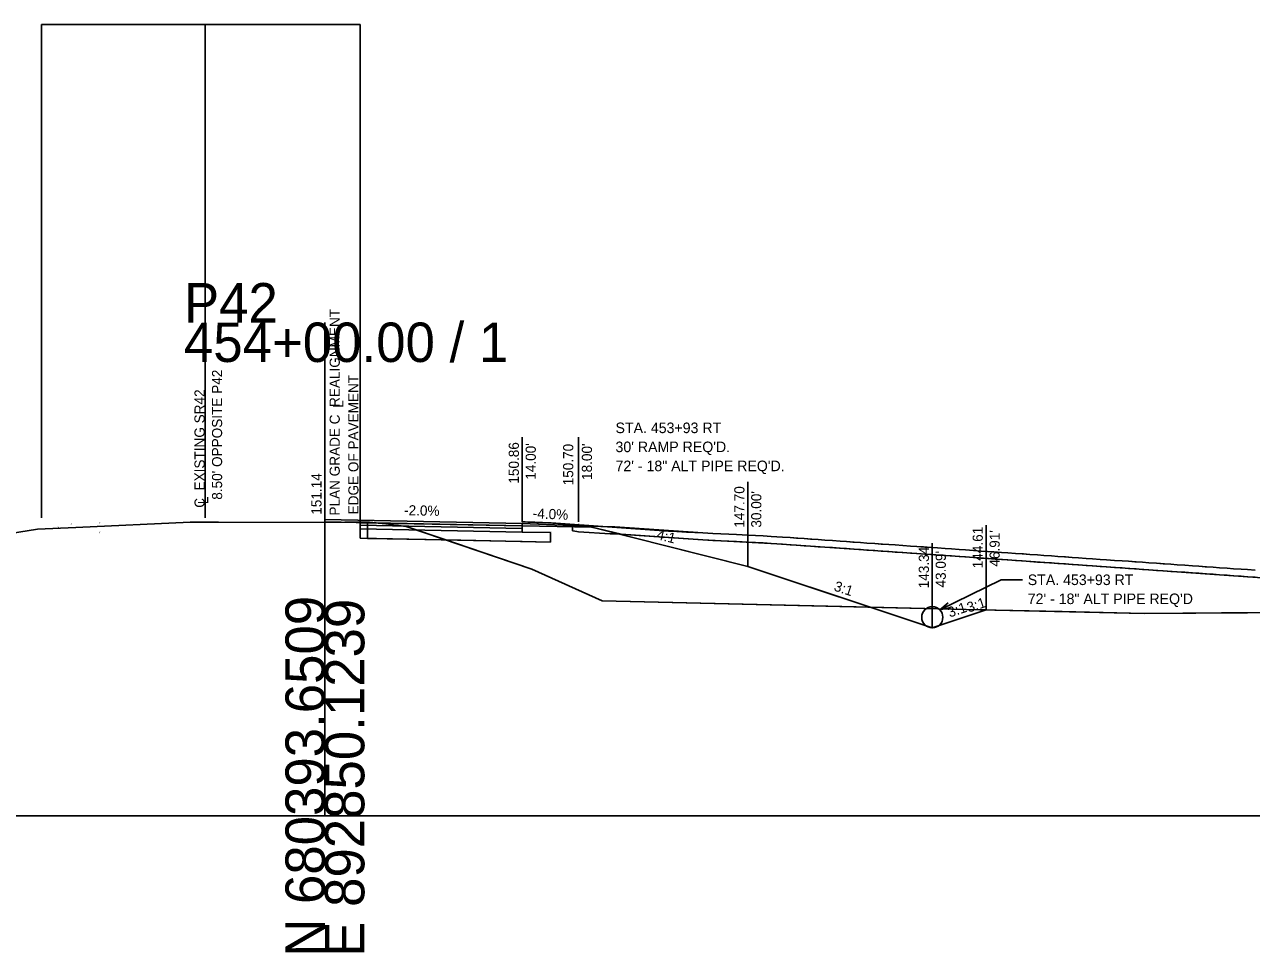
# Model space of a CAD drawing. Extents: x -26 to 4303, y -13 to 10775.
# Drawn here: x 128.7 to 215.7, y 2490.3 to 2556.1 of the extents above; entities that cross this region are included whole.
import ezdxf

# ---------------------------------------------------------------- set-up
doc = ezdxf.new("R2010")
doc.units = 0
for name, color, linetype in [('_CIVIL_CONSTRUCTION', 7, 'Continuous'), ('ASHPALT_12_5MM1', 7, 'Continuous'), ('CONST_DCH', 7, 'Continuous'), ('CONST_LV3', 7, 'Continuous'), ('Default', 7, 'Continuous'), ('DTM_CORRIDOR', 7, 'Continuous'), ('DTM_P_FINISHED_GRADE', 7, 'Continuous'), ('DTM_TEMP_DROP', 7, 'Continuous'), ('DTM_X_GROUND', 7, 'Continuous'), ('SLOPE_STAKES_FILL', 7, 'Continuous'), ('X_ROW', 7, 'Continuous'), ('X_TRANS_EOP', 7, 'Continuous'), ('XS_CELL', 7, 'Continuous'), ('XS_M_EXCAVATION_LIMITS', 7, 'Continuous'), ('XS_P_DR_GRAVEL', 7, 'Continuous'), ('XS_P_DRAINAGE', 7, 'Continuous'), ('XS_P_GROUND', 7, 'Continuous'), ('XS_P_SUBGRADE_MILLING', 7, 'Continuous'), ('XS_P_TX_CLEARZONE', 7, 'Continuous'), ('XS_P_TX_FS_BS', 7, 'Continuous'), ('XS_SHEET_EW_TX_AREA', 7, 'Continuous')]:
    doc.layers.add(name, color=color, linetype=linetype)

msp = doc.modelspace()

# ---------------------------------------------------------------- linework, layer by layer
msp.add_line((164, 2520.382), (164, 2520.132))
msp.add_lwpolyline([(152.49, 2520.613), (164, 2520.382), (164, 2520.57), (164, 2520.57), (152.49, 2520.8)])
at = {"layer": 'ASHPALT_12_5MM1'}
for p, q in [((164, 2520.736), (150, 2521.016)), ((164, 2520.57), (164, 2520.736))]:
    msp.add_line(p, q, dxfattribs=at)
at = {"layer": 'CONST_LV3'}
for points in [[(164, 2520.861), (164.203, 2520.853), (164.898, 2520.826), (165.026, 2520.82), (165.203, 2520.813), (165.819, 2520.789), (166.046, 2520.78), (174.373, 2520.208), (174.963, 2520.184), (175.657, 2520.134), (176.23, 2520.111), (176.802, 2520.088), (177.53, 2520.038), (178.089, 2520.016), (178.649, 2519.994), (179.208, 2519.971), (180, 2519.921), (180.55, 2519.899), (181.1, 2519.86), (181.65, 2519.822), (182.453, 2519.776), (183, 2519.737), (183.547, 2519.699), (184, 2519.667), (184.547, 2519.629), (185, 2519.597), (185.453, 2519.566), (186, 2519.527), (186.547, 2519.489), (187, 2519.457), (187.453, 2519.426), (188, 2519.387), (188.453, 2519.356), (189, 2519.317), (189.547, 2519.279), (190, 2519.247), (190.453, 2519.216), (191, 2519.177), (191.547, 2519.139), (192, 2519.107), (192.453, 2519.076), (193, 2519.037), (193.453, 2519.006), (194, 2518.967), (194.453, 2518.936), (195, 2518.897), (195.453, 2518.866), (196, 2518.827), (196.547, 2518.789), (197, 2518.757), (197.453, 2518.726), (198, 2518.687), (198.453, 2518.656), (199, 2518.617), (199.547, 2518.579), (200, 2518.547), (200.547, 2518.509), (201, 2518.477), (201.547, 2518.439), (202, 2518.407), (202.453, 2518.376), (203, 2518.337), (203.453, 2518.306), (204, 2518.267), (204.453, 2518.236), (205, 2518.197), (205.453, 2518.166), (206, 2518.127), (206.547, 2518.089), (207, 2518.057), (207.453, 2518.026), (208, 2517.987), (208.453, 2517.956), (209, 2517.917), (209.547, 2517.879), (210, 2517.847), (210.453, 2517.816), (211, 2517.777), (211.547, 2517.739), (212, 2517.707), (212.453, 2517.676), (213, 2517.637), (213.453, 2517.606), (214, 2517.567), (214.453, 2517.536), (215, 2517.497), (215.453, 2517.466), (216, 2517.427)], [(173.72, 2519.271), (180, 2517.701)]]:
    msp.add_lwpolyline(points, dxfattribs=at)
at = {"layer": 'Default'}
msp.add_lwpolyline([(150, 2521.016), (150, 2521.016), (150, 2521.016), (150, 2520.85), (150, 2520.85), (164, 2520.57), (164, 2520.736), (164, 2520.736), (150, 2521.016)], dxfattribs=at)
at = {"layer": 'DTM_P_FINISHED_GRADE'}
msp.add_lwpolyline([(164, 2520.861), (164.406, 2520.845), (165.43, 2520.803), (168, 2520.646)], dxfattribs=at)
at = {"layer": 'DTM_X_GROUND'}
msp.add_lwpolyline([(126.483, 2519.853), (129.624, 2520.342), (132.328, 2520.454), (140.446, 2520.825), (142.449, 2520.836), (150.002, 2520.811), (150.026, 2520.811), (153.025, 2520.845), (153.314, 2520.82), (154.313, 2520.72), (155.766, 2520.524), (164.68, 2517.505), (169.665, 2515.248), (196.459, 2514.625), (208.123, 2514.36), (219.103, 2514.434), (224.908, 2514.43), (258.789, 2514.528), (262.204, 2514.527), (283.454, 2514.615), (299.495, 2514.392), (300, 2514.385)], dxfattribs=at)
at = {"layer": 'X_ROW'}
for p, q in [((164, 2520.861), (164, 2520.861)), ((164, 2520.861), (164, 2520.861)), ((164, 2520.57), (164, 2520.736)), ((164, 2520.736), (168.595, 2520.553)), ((168.925, 2520.47), (164, 2520.57)), ((164, 2520.57), (164, 2520.57)), ((166, 2520.781), (166, 2520.781)), ((168, 2520.701), (168, 2520.701)), ((168.595, 2520.553), (168.925, 2520.47))]:
    msp.add_line(p, q, dxfattribs=at)
for points in [[(164, 2519.466), (166, 2519.426), (165.995, 2520.092), (165.995, 2520.092), (164, 2520.132), (164, 2520.132), (152.49, 2520.363)], [(152.49, 2519.696), (164, 2519.466), (164, 2519.466)]]:
    msp.add_lwpolyline(points, dxfattribs=at)
at = {"layer": 'X_TRANS_EOP'}
for p, q in [((129.887, 2521.141), (129.887, 2556.141)), ((129.887, 2556.141), (152.49, 2556.141)), ((141.5, 2521.141), (141.5, 2556.141)), ((152.49, 2521.141), (152.49, 2556.141))]:
    msp.add_line(p, q, dxfattribs=at)
at = {"layer": 'XS_CELL'}
for p, q in [((150, 2500), (150, 2535)), ((0, 2500), (150, 2500)), ((150, 2500), (300, 2500))]:
    msp.add_line(p, q, dxfattribs=at)
at = {"layer": 'XS_M_EXCAVATION_LIMITS'}
msp.add_line((152.49, 2519.696), (152.49, 2533.604), dxfattribs=at)
at = {"layer": 'XS_P_DR_GRAVEL'}
for p, q in [((167.575, 2520.216), (167.575, 2520.593)), ((170.242, 2520.51), (167.575, 2520.593)), ((170.242, 2520.51), (170.562, 2520.497)), ((170.562, 2520.497), (176.802, 2520.088)), ((167.58, 2520.215), (167.575, 2520.216)), ((167.583, 2520.215), (167.58, 2520.215)), ((167.607, 2520.214), (167.583, 2520.215)), ((168, 2520.146), (167.607, 2520.214)), ((170.242, 2520.01), (168, 2520.146)), ((170.562, 2519.997), (170.242, 2520.01)), ((176.802, 2519.588), (170.562, 2519.997)), ((176.802, 2520.088), (177.53, 2520.038)), ((177.53, 2520.038), (178.089, 2520.016)), ((178.089, 2520.016), (178.649, 2519.994)), ((178.649, 2519.994), (179.208, 2519.971)), ((179.208, 2519.971), (180, 2519.921)), ((180, 2519.921), (180.55, 2519.899)), ((180.55, 2519.899), (181.1, 2519.86)), ((181.1, 2519.86), (181.65, 2519.822)), ((181.65, 2519.822), (182.453, 2519.776)), ((182.453, 2519.776), (183, 2519.737)), ((183, 2519.737), (183.453, 2519.706)), ((183.453, 2519.706), (184, 2519.667)), ((184, 2519.667), (184.453, 2519.636)), ((184.453, 2519.636), (185, 2519.597)), ((177.53, 2519.538), (176.802, 2519.588)), ((178.089, 2519.516), (177.53, 2519.538)), ((178.649, 2519.494), (178.089, 2519.516)), ((179.208, 2519.471), (178.649, 2519.494)), ((180, 2519.421), (179.208, 2519.471)), ((180.55, 2519.399), (180, 2519.421)), ((181.1, 2519.36), (180.55, 2519.399)), ((181.65, 2519.322), (181.1, 2519.36)), ((182.453, 2519.276), (181.65, 2519.322)), ((183, 2519.237), (182.453, 2519.276)), ((183.453, 2519.206), (183, 2519.237)), ((184, 2519.167), (183.453, 2519.206)), ((184.453, 2519.136), (184, 2519.167)), ((185, 2519.097), (184.453, 2519.136)), ((185, 2519.597), (185.453, 2519.566)), ((185.453, 2519.066), (185, 2519.097)), ((185.453, 2519.566), (186, 2519.527)), ((186, 2519.027), (185.453, 2519.066)), ((186, 2519.527), (186.547, 2519.489)), ((186.547, 2518.989), (186, 2519.027)), ((186.547, 2519.489), (187, 2519.457)), ((187, 2518.957), (186.547, 2518.989)), ((187, 2519.457), (187.547, 2519.419)), ((187.547, 2518.919), (187, 2518.957)), ((187.547, 2519.419), (188, 2519.387)), ((188, 2518.887), (187.547, 2518.919)), ((188, 2519.387), (188.453, 2519.356)), ((188.453, 2518.856), (188, 2518.887)), ((188.453, 2519.356), (189, 2519.317)), ((189, 2518.817), (188.453, 2518.856)), ((189, 2519.317), (189.453, 2519.286)), ((189.453, 2518.786), (189, 2518.817)), ((189.453, 2519.286), (190, 2519.247)), ((190, 2518.747), (189.453, 2518.786)), ((190, 2519.247), (190.453, 2519.216)), ((190.453, 2518.716), (190, 2518.747)), ((190.453, 2519.216), (191, 2519.177)), ((191, 2519.177), (191.547, 2519.139)), ((191.547, 2519.139), (192, 2519.107)), ((192, 2519.107), (192.547, 2519.069)), ((192.547, 2519.069), (193, 2519.037)), ((193, 2519.037), (193.453, 2519.006)), ((193.453, 2519.006), (194, 2518.967)), ((194, 2518.967), (194.453, 2518.936)), ((194.453, 2518.936), (195, 2518.897)), ((195, 2518.897), (195.453, 2518.866)), ((195.453, 2518.866), (196, 2518.827)), ((196, 2518.827), (196.547, 2518.789)), ((196.547, 2518.789), (197, 2518.757)), ((197, 2518.757), (197.547, 2518.719)), ((191, 2518.677), (190.453, 2518.716)), ((191.547, 2518.639), (191, 2518.677)), ((192, 2518.607), (191.547, 2518.639)), ((192.547, 2518.569), (192, 2518.607)), ((193, 2518.537), (192.547, 2518.569)), ((193.453, 2518.506), (193, 2518.537)), ((194, 2518.467), (193.453, 2518.506)), ((194.453, 2518.436), (194, 2518.467)), ((195, 2518.397), (194.453, 2518.436)), ((195.453, 2518.366), (195, 2518.397)), ((196, 2518.327), (195.453, 2518.366)), ((196.547, 2518.289), (196, 2518.327)), ((197, 2518.257), (196.547, 2518.289)), ((197.547, 2518.219), (197, 2518.257)), ((197.547, 2518.719), (198, 2518.687)), ((198, 2518.187), (197.547, 2518.219)), ((198, 2518.687), (198.453, 2518.656)), ((198.453, 2518.156), (198, 2518.187)), ((198.453, 2518.656), (199, 2518.617)), ((199, 2518.117), (198.453, 2518.156)), ((199, 2518.617), (199.453, 2518.586)), ((199.453, 2518.086), (199, 2518.117)), ((199.453, 2518.586), (200, 2518.547)), ((200, 2518.047), (199.453, 2518.086)), ((200, 2518.547), (200.547, 2518.509)), ((200.547, 2518.009), (200, 2518.047)), ((200.547, 2518.509), (201, 2518.477)), ((201, 2517.977), (200.547, 2518.009)), ((201, 2518.477), (201.547, 2518.439)), ((201.547, 2517.939), (201, 2517.977)), ((201.547, 2518.439), (202, 2518.407)), ((202, 2517.907), (201.547, 2517.939)), ((202, 2518.407), (202.547, 2518.369)), ((202.547, 2517.869), (202, 2517.907)), ((202.547, 2518.369), (203, 2518.337)), ((203, 2517.837), (202.547, 2517.869)), ((203, 2518.337), (203.453, 2518.306)), ((203.453, 2518.306), (204, 2518.267)), ((204, 2518.267), (204.453, 2518.236)), ((204.453, 2518.236), (205, 2518.197)), ((205, 2518.197), (205.453, 2518.166)), ((205.453, 2518.166), (206, 2518.127)), ((206, 2518.127), (206.547, 2518.089)), ((206.547, 2518.089), (207, 2518.057)), ((207, 2518.057), (207.547, 2518.019)), ((207.547, 2518.019), (208, 2517.987)), ((208, 2517.987), (208.453, 2517.956)), ((208.453, 2517.956), (209, 2517.917)), ((209, 2517.917), (209.453, 2517.886)), ((209.453, 2517.886), (210, 2517.847)), ((203.453, 2517.806), (203, 2517.837)), ((204, 2517.767), (203.453, 2517.806)), ((204.453, 2517.736), (204, 2517.767)), ((205, 2517.697), (204.453, 2517.736)), ((205.453, 2517.666), (205, 2517.697)), ((206, 2517.627), (205.453, 2517.666)), ((206.547, 2517.589), (206, 2517.627)), ((207, 2517.557), (206.547, 2517.589)), ((207.547, 2517.519), (207, 2517.557)), ((208, 2517.487), (207.547, 2517.519)), ((208.453, 2517.456), (208, 2517.487)), ((209, 2517.417), (208.453, 2517.456)), ((209.453, 2517.386), (209, 2517.417)), ((210, 2517.347), (209.453, 2517.386)), ((210, 2517.847), (210.453, 2517.816)), ((210.453, 2517.316), (210, 2517.347)), ((210.453, 2517.816), (211, 2517.777)), ((211, 2517.277), (210.453, 2517.316)), ((211, 2517.777), (211.547, 2517.739)), ((211.547, 2517.239), (211, 2517.277)), ((211.547, 2517.739), (212, 2517.707)), ((212, 2517.207), (211.547, 2517.239)), ((212, 2517.707), (212.547, 2517.669)), ((212.547, 2517.169), (212, 2517.207)), ((212.547, 2517.669), (213, 2517.637)), ((213, 2517.137), (212.547, 2517.169)), ((213, 2517.637), (213.453, 2517.606)), ((213.453, 2517.106), (213, 2517.137)), ((213.453, 2517.606), (214, 2517.567)), ((214, 2517.067), (213.453, 2517.106)), ((214, 2517.567), (214.453, 2517.536)), ((214.453, 2517.036), (214, 2517.067)), ((214.453, 2517.536), (215, 2517.497)), ((215, 2516.997), (214.453, 2517.036)), ((215, 2517.497), (215.453, 2517.466)), ((215.453, 2516.966), (215, 2516.997)), ((215.453, 2517.466), (216, 2517.427)), ((216, 2516.927), (215.453, 2516.966))]:
    msp.add_line(p, q, dxfattribs=at)
at = {"layer": 'XS_P_DRAINAGE'}
for p in [(193.615, 2514.621), (199.482, 2516.748)]:
    msp.add_line(p, (197.982, 2516.748), dxfattribs=at)
msp.add_lwpolyline([(194.372, 2514.781), (193.615, 2514.621), (194.208, 2515.118)], dxfattribs=at)
msp.add_circle((193.085, 2514.09), 0.75, dxfattribs=at)
at = {"layer": 'XS_P_GROUND'}
for points in [[(193.085, 2513.34), (193.085, 2513.34), (180, 2517.701), (168.925, 2520.47)], [(193.085, 2513.34), (196.909, 2514.615)]]:
    msp.add_lwpolyline(points, dxfattribs=at)
at = {"layer": 'XS_P_SUBGRADE_MILLING'}
msp.add_lwpolyline([(152.971, 2520.353), (153.04, 2520.352)], dxfattribs=at)
at = {"layer": 'XS_P_TX_CLEARZONE'}
for p, q in [((141.5, 2521.141), (141.5, 2527.141)), ((150, 2521.141), (150, 2527.141)), ((150, 2521.141), (150, 2527.141)), ((150, 2521.141), (150, 2527.141)), ((164, 2520.861), (164, 2526.861)), ((164, 2520.861), (164, 2526.861)), ((164, 2520.861), (164, 2526.861)), ((168, 2520.861), (168, 2526.861)), ((180, 2517.701), (180, 2523.701)), ((180, 2517.701), (180, 2523.701)), ((180, 2517.701), (180, 2523.701)), ((196.909, 2514.615), (196.909, 2520.615)), ((196.909, 2514.615), (196.909, 2520.615)), ((196.909, 2514.615), (196.909, 2520.615)), ((193.085, 2513.34), (193.085, 2519.34)), ((193.085, 2513.34), (193.085, 2519.34)), ((193.085, 2513.34), (193.085, 2519.34))]:
    msp.add_line(p, q, dxfattribs=at)
at = {"layer": 'XS_SHEET_EW_TX_AREA'}
for points in [[(151.403, 2520.824), (153.025, 2520.789), (153.025, 2519.685), (158.57, 2519.575), (155.766, 2520.524), (154.313, 2520.72), (153.169, 2520.832), (153.025, 2520.845), (151.525, 2520.828)], [(188.689, 2514.805), (169.665, 2515.248), (164.68, 2517.505), (160.223, 2519.015), (158.57, 2519.575), (166, 2519.426), (165.995, 2520.092), (164, 2520.132), (164, 2520.57), (168.925, 2520.47), (174.463, 2519.086), (180, 2517.701)], [(168.925, 2520.47), (180, 2517.701), (188.689, 2514.805), (196.459, 2514.625), (202.291, 2514.493), (208.123, 2514.36), (213.613, 2514.397), (224.908, 2514.43), (241.848, 2514.479), (250.675, 2514.487), (212.773, 2517.153), (195.727, 2518.346), (182.052, 2519.299), (176.802, 2519.588), (171.025, 2519.989)], [(196.909, 2514.615), (193.085, 2513.34), (188.689, 2514.805), (196.459, 2514.625)]]:
    msp.add_lwpolyline(points, close=True, dxfattribs=at)

# ---------------------------------------------------------------- texts
at = {"layer": '_CIVIL_CONSTRUCTION'}
for height, p in [(0.001, (141.5, 2542.212)), (0.12, (131.036, 2520.41)), (0.12, (133.961, 2520.721)), (0.12, (149.961, 2521.081)), (0.12, (163.961, 2520.801)), (0.12, (168.886, 2520.41)), (0.12, (133.966, 2520.032)), (0.12, (165.955, 2520.032))]:
    msp.add_text('X', height=height, dxfattribs=at).set_placement(p)
at = {"layer": 'CONST_DCH'}
msp.add_text('X', height=0.12, dxfattribs=at).set_placement((193.046, 2513.28))
msp.add_text('X', height=0.12, dxfattribs=at).set_placement((193.046, 2513.28))
at = {"layer": 'DTM_CORRIDOR'}
msp.add_text('X', height=0.12, dxfattribs=at).set_placement((196.87, 2514.555))
at = {"layer": 'DTM_TEMP_DROP'}
for p in [(131.961, 2520.641), (167.961, 2520.641)]:
    msp.add_text('X', height=0.12, dxfattribs=at).set_placement(p)
at = {"layer": 'SLOPE_STAKES_FILL'}
msp.add_text('X', height=0.12, dxfattribs=at).set_placement((179.961, 2517.641))
at = {"layer": 'XS_CELL'}
for s, p in [('P42', (140, 2535)), ('454+00.00 / 1', (140, 2532.2))]:
    msp.add_text(s, height=2.8, dxfattribs=at).set_placement(p)
for s, p in [('N 680393.6509', (150, 2490)), ('E 892850.1239', (152.8, 2490))]:
    msp.add_text(s, height=2.8, rotation=90, dxfattribs=at).set_placement(p)
at = {"layer": 'XS_P_DRAINAGE'}
for s, p in [('STA. 453+93 RT', (170.615, 2527.153)), ("30' RAMP REQ'D.", (170.615, 2525.803)), ('72\' - 18" ALT PIPE REQ\'D.', (170.615, 2524.453)), ('STA. 453+93 RT', (199.857, 2516.373)), ('72\' - 18" ALT PIPE REQ\'D', (199.857, 2515.023))]:
    msp.add_text(s, height=0.75, dxfattribs=at).set_placement(p)
at = {"layer": 'XS_P_TX_CLEARZONE'}
for s, p in [('PLAN GRADE C  REALIGNMENT', (151.056, 2521.305)), ("8.50' OPPOSITE P42", (142.71, 2522.427)), ('EDGE OF PAVEMENT', (152.381, 2521.39)), ('C  EXISTING SR42', (141.47, 2521.855)), ('L', (151.306, 2528.945)), ('150.86', (163.76, 2523.569)), ('150.86', (163.76, 2523.569)), ('150.86', (163.76, 2523.569)), ("14.00'", (164.96, 2523.847)), ("14.00'", (164.96, 2523.847)), ("14.00'", (164.96, 2523.847)), ('150.70', (167.619, 2523.45)), ("18.00'", (168.947, 2523.831)), ('151.14', (149.76, 2521.362)), ('151.14', (149.76, 2521.362)), ('151.14', (149.76, 2521.362)), ('147.70', (179.76, 2520.443)), ('147.70', (179.76, 2520.443)), ('147.70', (179.76, 2520.443)), ('L', (141.72, 2522.107)), ("30.00'", (180.96, 2520.449)), ("30.00'", (180.96, 2520.449)), ("30.00'", (180.96, 2520.449)), ('144.61', (196.669, 2517.566)), ('144.61', (196.669, 2517.566)), ('144.61', (196.669, 2517.566)), ("46.91'", (197.869, 2517.68)), ("46.91'", (197.869, 2517.68)), ("46.91'", (197.869, 2517.68)), ('143.34', (192.845, 2516.144)), ('143.34', (192.845, 2516.144)), ('143.34', (192.845, 2516.144)), ("43.09'", (194.045, 2516.201)), ("43.09'", (194.045, 2516.201)), ("43.09'", (194.045, 2516.201))]:
    msp.add_text(s, height=0.72, rotation=90, dxfattribs=at).set_placement(p)
at = {"layer": 'XS_P_TX_FS_BS'}
for s, rotation, p in [('-2.0%', 358.85424, (155.61, 2521.329)), ('-4.0%', 357.46748, (164.733, 2521.114)), ('4:1', 345.96376, (173.479, 2519.641)), ('3:1', 341.56677, (186.057, 2515.999)), ('3:1', 18.43493, (195.678, 2514.412)), ('3:1', 18.43493, (194.321, 2514.069))]:
    msp.add_text(s, height=0.72, rotation=rotation, dxfattribs=at).set_placement(p)

doc.saveas('drawing.dxf')
